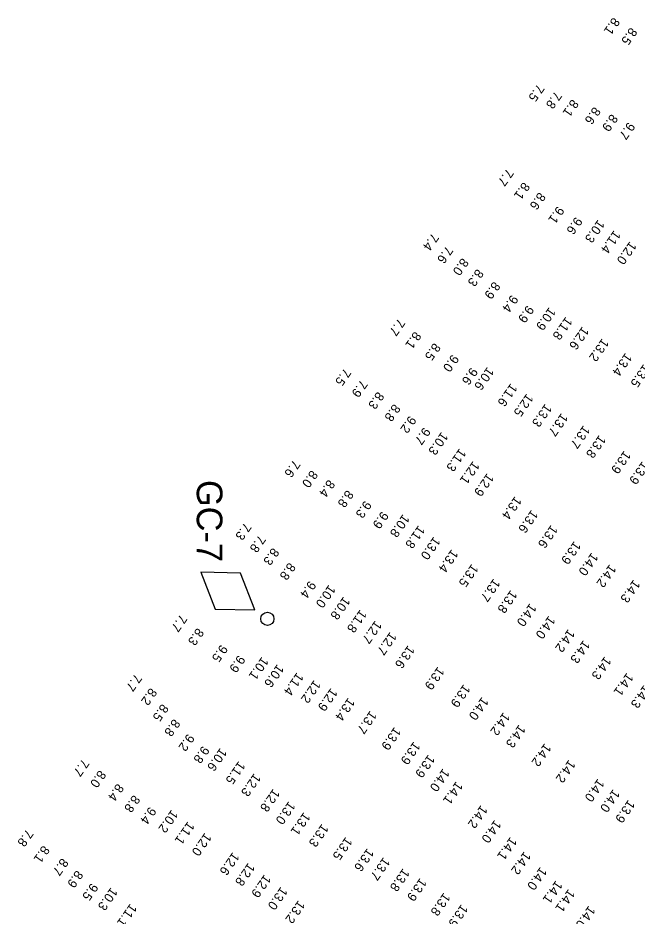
# Model space of a CAD drawing. Extents: x 815385 to 820851, y 582449 to 604245.
# Drawn here: x 817405.8 to 817743.8, y 585461.7 to 585951.9 of the extents above; entities that cross this region are included whole.
import ezdxf

# ---------------------------------------------------------------- set-up
doc = ezdxf.new("R2010")
doc.units = 0
for name, color, linetype in [('V-CHAN-AIDS', 7, 'Continuous'), ('V-TOPO-SOUN-021509', 7, 'Continuous'), ('V-TOPO-SOUN-101408', 7, 'Continuous')]:
    doc.layers.add(name, color=color, linetype=linetype)

msp = doc.modelspace()

# ---------------------------------------------------------------- linework, layer by layer
at = {"layer": 'V-CHAN-AIDS'}
msp.add_lwpolyline([(817535.05, 585628.76), (817527.19, 585648.91), (817505.56, 585649.41), (817513.42, 585629.25)], close=True, dxfattribs=at)
msp.add_circle((817541.93, 585623.94), 3.6, dxfattribs=at)

# ---------------------------------------------------------------- texts
msp.add_text('GC-7', height=14, rotation=270, dxfattribs=at).set_placement((817503.38, 585699.7))
at = {"layer": 'V-TOPO-SOUN-021509'}
for s, p in [('8.1', (817730.76, 585952.56)), ('8.5', (817740.23, 585947.11)), ('7.5', (817689.5, 585916.17)), ('7.8', (817699.06, 585912.21)), ('8.1', (817708.25, 585907.87)), ('8.6', (817720.27, 585903.76)), ('8.9', (817729.69, 585899.83)), ('9.7', (817739.03, 585895.44)), ('7.7', (817672.75, 585870.02)), ('8.1', (817681.65, 585862.65)), ('8.6', (817690.24, 585857.11)), ('9.1', (817700.38, 585849.51)), ('9.6', (817710.28, 585843.66)), ('10.3 ', (817722.5, 585842.11)), ('7.4', (817631.9, 585834.79)), ('11.4 ', (817731.26, 585836.32)), ('7.6', (817639.66, 585827.78)), ('12.0 ', (817739.9, 585830.27)), ('8.0', (817648.21, 585821.23)), ('8.3', (817656.39, 585815.25)), ('8.9', (817665.48, 585808.35)), ('9.4', (817675.25, 585801.12)), ('9.9', (817683.85, 585795.39)), ('10.9 ', (817695.79, 585794.32)), ('7.7', (817613.5, 585788.24)), ('11.8 ', (817704.88, 585789.09)), ('12.6 ', (817713.94, 585783.75)), ('8.1', (817622.31, 585781.12)), ('8.5', (817632.9, 585774.85)), ('13.2 ', (817724.77, 585777.29)), ('9.0', (817642.86, 585768.57)), ('13.4 ', (817737.48, 585769.39)), ('13.5 ', (817747.38, 585763.23)), ('7.5', (817583.99, 585761.03)), ('9.6', (817653.17, 585761.51)), ('10.6 ', (817662.07, 585761.66)), ('7.9', (817592.98, 585754.72)), ('11.6 ', (817674.84, 585752.74)), ('8.3', (817602.05, 585748.24)), ('12.5 ', (817683.59, 585747.19)), ('8.8', (817610.93, 585741.55)), ('13.3 ', (817693.64, 585741.59)), ('9.2', (817619.58, 585735.13)), ('13.7 ', (817702.48, 585736.49)), ('9.7', (817627.38, 585728.81)), ('13.7 ', (817714.54, 585729.8)), ('10.3 ', (817637.04, 585726.25)), ('13.8 ', (817723.12, 585724.55)), ('11.3 ', (817646.87, 585717.25)), ('13.9 ', (817736.78, 585716.03)), ('7.6', (817556.27, 585711.03)), ('12.1 ', (817654.23, 585710.3)), ('13.9 ', (817746.67, 585710.19)), ('8.0', (817565.88, 585705.4)), ('8.4', (817575.22, 585700.24)), ('12.9 ', (817661.96, 585703.69)), ('8.8', (817585.36, 585694.55)), ('13.4 ', (817677.16, 585691.1)), ('9.3', (817595.17, 585688.77)), ('9.9', (817604.47, 585682.96)), ('10.8 ', (817616, 585681.32)), ('13.6 ', (817686.16, 585683.72)), ('7.3', (817529.52, 585676.74)), ('11.8 ', (817624.43, 585675.21)), ('13.6 ', (817696.87, 585675.46)), ('7.8', (817537.35, 585669.99)), ('13.0 ', (817632.83, 585669.1)), ('13.9 ', (817709.5, 585666.59)), ('8.3', (817544.76, 585663.04)), ('13.4 ', (817642.55, 585662.16)), ('14.0 ', (817719, 585660.37)), ('8.8', (817553.72, 585654.96)), ('13.5 ', (817653.58, 585654.19)), ('14.2 ', (817728.82, 585653.97)), ('13.7 ', (817665.48, 585646.16)), ('14.3 ', (817741.89, 585645.62)), ('9.4', (817564.87, 585645.05)), ('10.0 ', (817575.54, 585642.82)), ('10.8 ', (817583.55, 585636.35)), ('13.8 ', (817674.78, 585639.89)), ('14.0 ', (817685.28, 585632.68)), ('7.7', (817494.47, 585626.67)), ('11.8 ', (817592.6, 585629.27)), ('14.0 ', (817695.59, 585625.88)), ('12.7 ', (817600.84, 585623.27)), ('8.3', (817503.63, 585619.25)), ('12.7 ', (817608.94, 585617.03)), ('14.2 ', (817706.25, 585618.59)), ('14.3 ', (817714.53, 585612.56)), ('9.5', (817516.63, 585610.17)), ('13.6 ', (817618.78, 585609.78)), ('9.9', (817526.17, 585604.42)), ('10.1 ', (817538.97, 585603.47)), ('14.3 ', (817726.14, 585603.68)), ('10.6 ', (817547.38, 585599.42)), ('13.9 ', (817635.01, 585598.07)), ('7.7', (817469.75, 585594.2)), ('11.4 ', (817558.11, 585594.94)), ('14.1 ', (817738.22, 585594.74)), ('8.2', (817478.02, 585586.58)), ('12.2 ', (817567.47, 585590.79)), ('12.9 ', (817576.64, 585586.42)), ('13.9 ', (817649.15, 585588.48)), ('14.3 ', (817747.53, 585588.06)), ('14.0 ', (817659.11, 585581.54)), ('8.5', (817484.36, 585577.83)), ('13.4 ', (817586.1, 585581.15)), ('13.7 ', (817598.06, 585574.03)), ('14.2 ', (817670.84, 585573.16)), ('8.8', (817490.71, 585569.6)), ('13.9 ', (817611.35, 585565.16)), ('14.3 ', (817679.34, 585566.44)), ('9.2', (817498.48, 585561.49)), ('13.9 ', (817621.9, 585557.23)), ('9.8', (817506.62, 585554.88)), ('10.6 ', (817516.23, 585553.74)), ('14.2 ', (817693.34, 585556.24)), ('13.9 ', (817629.81, 585550.08)), ('14.2 ', (817706.57, 585547.3)), ('11.5 ', (817526.31, 585546.52)), ('14.0 ', (817637.84, 585542.52)), ('12.3 ', (817534.75, 585539.87)), ('14.1 ', (817645.07, 585535.49)), ('14.0 ', (817722.38, 585536.93)), ('12.8 ', (817545.16, 585531.45)), ('14.0 ', (817730.78, 585531.21)), ('13.0 ', (817553.64, 585524.59)), ('13.9 ', (817739.04, 585525.42)), ('13.1 ', (817561.85, 585518.63)), ('14.2 ', (817658.57, 585522.48)), ('14.0 ', (817666.04, 585514.45)), ('13.3 ', (817571.73, 585512.28)), ('13.5 ', (817584.75, 585505.15)), ('14.1 ', (817674.61, 585505.13)), ('13.6 ', (817596.51, 585498.95)), ('13.7 ', (817605.35, 585494.07)), ('14.2 ', (817682.19, 585497.23)), ('14.0 ', (817690.97, 585488.75)), ('13.8 ', (817616.02, 585487.98)), ('13.9 ', (817625.33, 585482.7)), ('14.1 ', (817699.49, 585481.37)), ('13.8 ', (817638.26, 585474.67)), ('14.1 ', (817706.34, 585476.69)), ('13.9 ', (817647.89, 585468.39)), ('14.0 ', (817717.43, 585467.62))]:
    msp.add_text(s, height=5, rotation=234.911, dxfattribs=at).set_placement(p)
at = {"layer": 'V-TOPO-SOUN-101408'}
for s, p in [('7.7', (817441.01, 585547.75)), ('8.0', (817450.2, 585541.63)), ('8.4', (817459.94, 585534.32)), ('8.8', (817468.81, 585528.08)), ('9.4', (817477.62, 585521.66)), ('10.2 ', (817489.59, 585519.99)), ('11.1 ', (817498.56, 585513.62)), ('7.8', (817410.52, 585509.4)), ('12.0 ', (817507.83, 585507.38)), ('8.1', (817419.42, 585500.52)), ('8.7', (817429.68, 585493.62)), ('12.6 ', (817523.07, 585496.85)), ('12.8 ', (817531.5, 585490.99)), ('8.9', (817437.71, 585486.97)), ('12.9 ', (817540.31, 585484.62)), ('9.5', (817445.89, 585480.01)), ('10.3 ', (817456.56, 585477.61)), ('13.0 ', (817549.32, 585477.93)), ('11.1 ', (817467.09, 585468.75)), ('13.2 ', (817558.89, 585470.52))]:
    msp.add_text(s, height=5, rotation=234.911, dxfattribs=at).set_placement(p)

doc.saveas('drawing.dxf')
